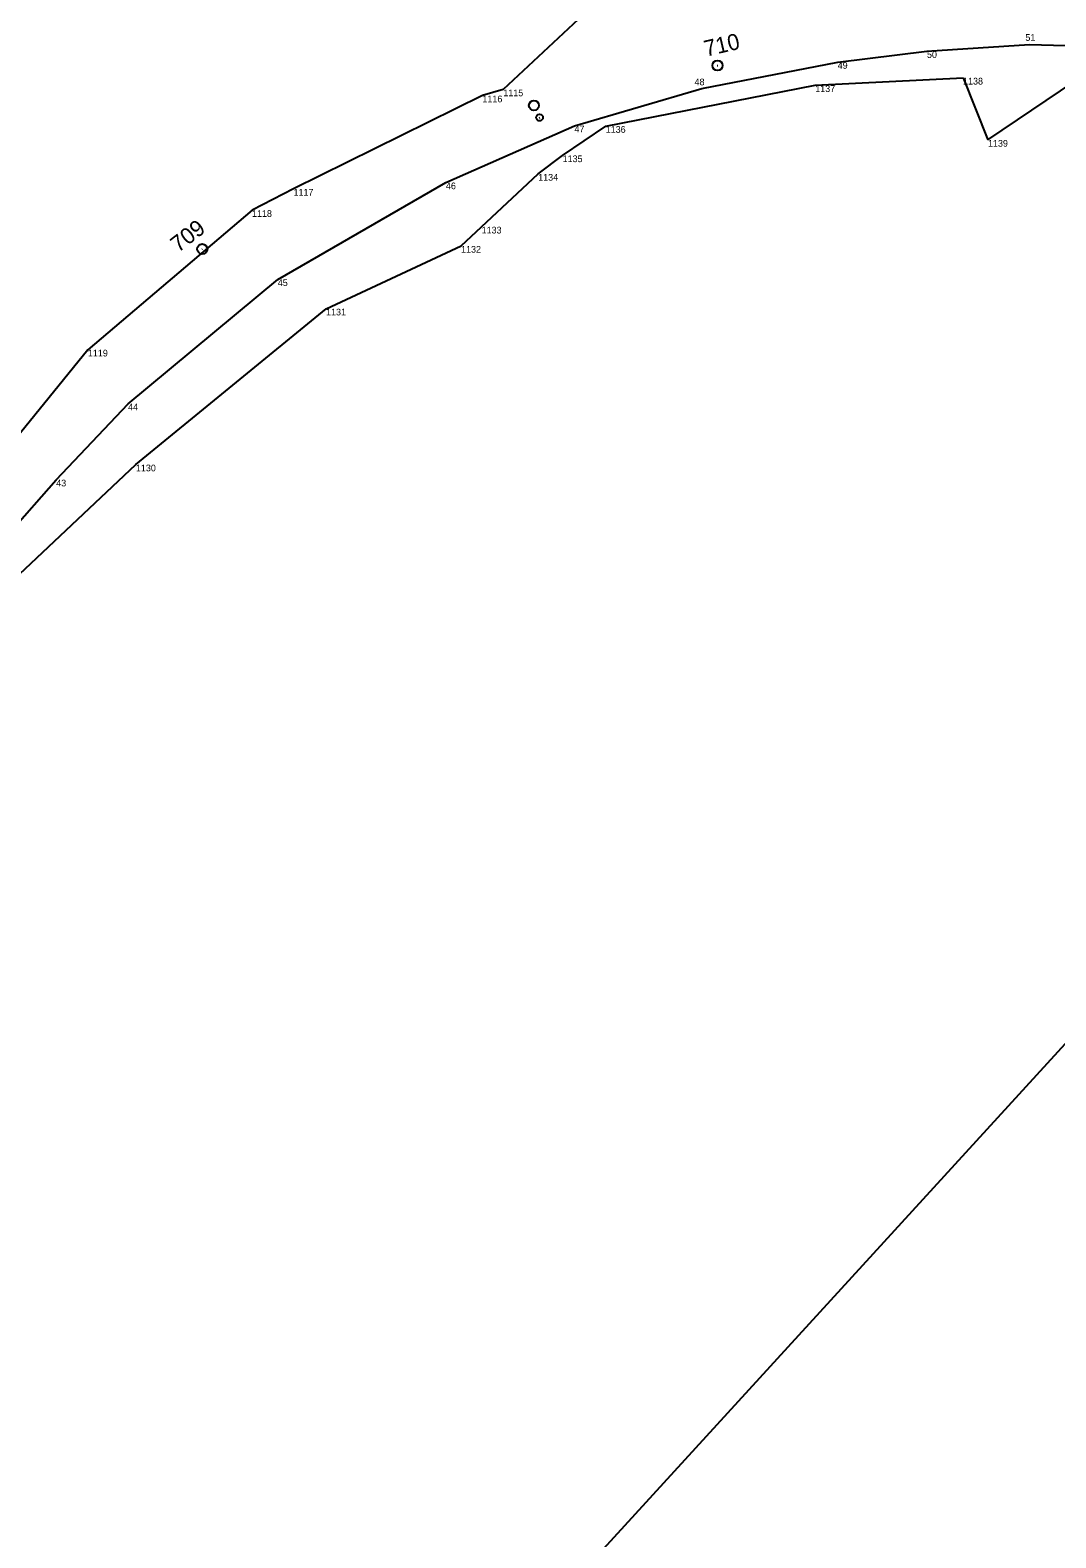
# Model space of a CAD drawing. Extents: x -678683 to -677755, y -1006946 to -1005971.
# Drawn here: x -678203.3 to -678050.1, y -1006566.2 to -1006341.2 of the extents above; entities that cross this region are included whole.
import ezdxf

# ---------------------------------------------------------------- set-up
doc = ezdxf.new("R2010")
doc.units = 0
for name, color, linetype in [('rozpiska - Lichá Tisk', 7, 'Continuous'), ('SSZT nové - lomové body', 7, 'Continuous'), ('SSZT_nové', 7, 'Continuous'), ('Stávající ŽBP', 7, 'Continuous'), ('SŽDC', 7, 'Continuous'), ('SŽDC - body', 7, 'Continuous'), ('Vrstva 7', 7, 'Continuous')]:
    doc.layers.add(name, color=color, linetype=linetype)

msp = doc.modelspace()

# ---------------------------------------------------------------- linework, layer by layer
at = {"layer": 'rozpiska - Lichá Tisk'}
msp.add_line((-678180.35, -1006636.35), (-678038.61, -1006481.4), dxfattribs=at)
at = {"layer": 'SSZT nové - lomové body'}
for p, q in [((-678054.02, -1006343.3), (-678054.02, -1006343.3)), ((-678082.69, -1006345.92), (-678082.69, -1006345.92)), ((-678069.35, -1006344.3), (-678069.35, -1006344.3)), ((-678102.99, -1006349.89), (-678102.99, -1006349.89)), ((-678122.02, -1006355.42), (-678122.02, -1006355.42)), ((-678141.21, -1006363.9), (-678141.21, -1006363.9)), ((-678166.33, -1006378.36), (-678166.33, -1006378.36)), ((-678188.69, -1006396.92), (-678188.69, -1006396.92)), ((-678199.43, -1006408.27), (-678199.43, -1006408.27))]:
    msp.add_line(p, q, dxfattribs=at)
at = {"layer": 'SSZT_nové'}
for points in [[(-678199.43, -1006408.27), (-678188.69, -1006396.92), (-678166.33, -1006378.36), (-678141.21, -1006363.9), (-678122.02, -1006355.42), (-678102.99, -1006349.89), (-678082.69, -1006345.92), (-678069.35, -1006344.3), (-678054.02, -1006343.3), (-678039.76, -1006343.69), (-678028.1, -1006343.37), (-677988.11, -1006347.69), (-677946.88, -1006353.16), (-677923.77, -1006355.85)], [(-678276.52, -1006503.93), (-678257.42, -1006480.58), (-678238.83, -1006456.75), (-678223.79, -1006437.46), (-678213.31, -1006424.02), (-678199.43, -1006408.27)]]:
    msp.add_lwpolyline(points, dxfattribs=at)
at = {"layer": 'Stávající ŽBP'}
for p, q in [((-678100.69, -1006346.44), (-678100.59, -1006346.42)), ((-678177.65, -1006373.86), (-678177.57, -1006373.8))]:
    msp.add_line(p, q, dxfattribs=at)
for centre in [(-678100.64, -1006346.43), (-678177.61, -1006373.83)]:
    msp.add_circle(centre, 0.756, dxfattribs=at)
at = {"layer": 'SŽDC'}
for p, q in [((-678115.07, -1006333.55), (-678132.64, -1006350.02)), ((-678060.24, -1006357.55), (-678043.36, -1006346.1)), ((-678086.04, -1006349.39), (-678063.96, -1006348.27)), ((-678063.96, -1006348.27), (-678060.24, -1006357.55)), ((-678132.64, -1006350.02), (-678135.76, -1006350.92)), ((-678117.34, -1006355.48), (-678086.04, -1006349.39)), ((-678135.76, -1006350.92), (-678163.98, -1006364.86)), ((-678123.78, -1006359.86), (-678117.34, -1006355.48)), ((-678127.43, -1006362.62), (-678123.78, -1006359.86)), ((-678135.88, -1006370.51), (-678127.43, -1006362.62)), ((-678163.98, -1006364.86), (-678170.18, -1006368.03)), ((-678170.18, -1006368.03), (-678194.69, -1006388.87)), ((-678138.95, -1006373.37), (-678135.88, -1006370.51)), ((-678159.12, -1006382.74), (-678138.95, -1006373.37)), ((-678187.52, -1006406.01), (-678159.12, -1006382.74)), ((-678194.69, -1006388.87), (-678215.4, -1006414.33)), ((-678223.89, -1006440.18), (-678187.52, -1006406.01))]:
    msp.add_line(p, q, dxfattribs=at)
at = {"layer": 'SŽDC - body'}
for p, q in [((-678063.96, -1006348.27), (-678063.96, -1006348.27)), ((-678132.64, -1006350.02), (-678132.64, -1006350.02)), ((-678086.04, -1006349.39), (-678086.04, -1006349.39)), ((-678135.76, -1006350.92), (-678135.76, -1006350.92)), ((-678117.34, -1006355.48), (-678117.34, -1006355.48)), ((-678060.24, -1006357.55), (-678060.24, -1006357.55)), ((-678123.78, -1006359.86), (-678123.78, -1006359.86)), ((-678127.43, -1006362.62), (-678127.43, -1006362.62)), ((-678163.98, -1006364.86), (-678163.98, -1006364.86)), ((-678170.18, -1006368.03), (-678170.18, -1006368.03)), ((-678135.88, -1006370.51), (-678135.88, -1006370.51)), ((-678138.95, -1006373.37), (-678138.95, -1006373.37)), ((-678159.12, -1006382.74), (-678159.12, -1006382.74)), ((-678194.69, -1006388.87), (-678194.69, -1006388.87)), ((-678187.52, -1006406.01), (-678187.52, -1006406.01))]:
    msp.add_line(p, q, dxfattribs=at)
at = {"layer": 'Vrstva 7'}
msp.add_line((-678127.26, -1006354.23), (-678127.17, -1006354.2), dxfattribs=at)
for centre, radius in [((-678128.06, -1006352.39), 0.75), ((-678127.22, -1006354.21), 0.5)]:
    msp.add_circle(centre, radius, dxfattribs=at)

# ---------------------------------------------------------------- texts
at = {"layer": 'SSZT nové - lomové body'}
for s, p in [('51', (-678054.65, -1006342.75)), ('49', (-678082.69, -1006346.92)), ('50', (-678069.35, -1006345.3)), ('48', (-678104.07, -1006349.39)), ('47', (-678122.02, -1006356.42)), ('46', (-678141.21, -1006364.9)), ('45', (-678166.33, -1006379.36)), ('44', (-678188.69, -1006397.92)), ('43', (-678199.43, -1006409.27))]:
    msp.add_text(s, height=1, dxfattribs=at).set_placement(p)
at = {"layer": 'Stávající ŽBP'}
for s, rotation, p in [('710', 13.1929, (-678102.35, -1006345.13)), ('709', 37.5774, (-678181.19, -1006374.43))]:
    msp.add_text(s, height=2.4, rotation=rotation, dxfattribs=at).set_placement(p)
at = {"layer": 'SŽDC - body'}
for s, p in [('1138', (-678063.96, -1006349.27)), ('1115', (-678132.64, -1006351.02)), ('1137', (-678086.04, -1006350.39)), ('1116', (-678135.76, -1006351.92)), ('1136', (-678117.34, -1006356.48)), ('1139', (-678060.24, -1006358.55)), ('1135', (-678123.78, -1006360.86)), ('1134', (-678127.43, -1006363.62)), ('1117', (-678163.98, -1006365.86)), ('1118', (-678170.18, -1006369.03)), ('1133', (-678135.88, -1006371.51)), ('1132', (-678138.95, -1006374.37)), ('1131', (-678159.12, -1006383.74)), ('1119', (-678194.69, -1006389.87)), ('1130', (-678187.52, -1006407.01))]:
    msp.add_text(s, height=1, dxfattribs=at).set_placement(p)

doc.saveas('drawing.dxf')
